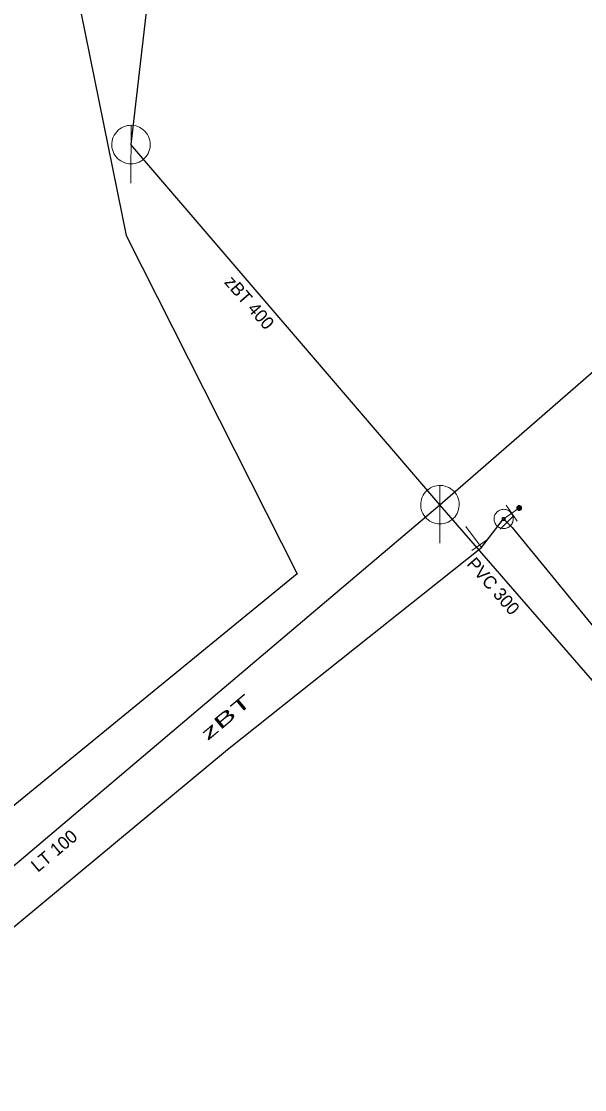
# Model space of a CAD drawing. Extents: x -688296 to -687852, y -973332 to -972816.
# Drawn here: x -688140.2 to -688111, y -973095.5 to -973040 of the extents above; entities that cross this region are included whole.
import ezdxf
from ezdxf.enums import TextEntityAlignment as Align

# ---------------------------------------------------------------- set-up
doc = ezdxf.new("R2010")
doc.units = 0
doc.header["$LTSCALE"] = 0.27
for name, color, linetype, lineweight in [('1', 7, 'Continuous', 25), ('13', 7, 'Continuous', 13), ('14', 7, 'Continuous', 13), ('17', 7, 'Continuous', 25), ('22', 7, 'Continuous', 13), ('34', 7, 'Continuous', 13), ('47', 7, 'Continuous', 13), ('9', 7, 'Continuous', 13)]:
    doc.layers.add(name, color=color, linetype=linetype, lineweight=lineweight)

msp = doc.modelspace()

# ---------------------------------------------------------------- linework, layer by layer
at = {"layer": '13'}
msp.add_line((-688116.42, -973067.199), (-688117.129, -973066.239), dxfattribs=at)
at = {"layer": '14', "lineweight": 25}
for p, q in [((-688134.528, -973046.412), (-688132.125, -973025.78)), ((-688118.48, -973065.11), (-688096.66, -973046.13)), ((-688118.48, -973065.11), (-688134.529, -973046.413)), ((-688141.707, -973084.764), (-688118.48, -973065.11))]:
    msp.add_line(p, q, dxfattribs=at)
at = {"layer": '14'}
for p, q in [((-688115.17, -973065.85), (-688114.989, -973066.03)), ((-688116.32, -973067.34), (-688116.42, -973067.199))]:
    msp.add_line(p, q, dxfattribs=at)
at = {"layer": '14', "lineweight": 25}
msp.add_lwpolyline([(-688102.469, -973083.96), (-688109.289, -973075.699), (-688118.48, -973065.109)], dxfattribs=at)
at = {"layer": '14'}
msp.add_lwpolyline([(-688115.17, -973065.85), (-688114.94, -973065.68), (-688114.75, -973065.55), (-688114.359, -973065.28)], dxfattribs=at)
at = {"layer": '17'}
for points in [[(-688123.609, -972815.609), (-688135.91, -972839.761), (-688146.524, -972867.704), (-688149.164, -972878.87), (-688150.368, -972974.473), (-688134.778, -973051.136), (-688125.903, -973068.701), (-688203.651, -973132.27), (-688148.612, -973199.748), (-688078.631, -973291.807), (-688049.631, -973331.642)], [(-688143.109, -973089.09), (-688129.52, -973077.82), (-688116.32, -973067.34), (-688115.17, -973065.85)], [(-688114.989, -973066.03), (-688114.73, -973066.289), (-688065.039, -973126.929)]]:
    msp.add_lwpolyline(points, dxfattribs=at)
at = {"layer": '22'}
for p, q in [((-688134.529, -973048.413), (-688134.528, -973045.413)), ((-688118.48, -973067.109), (-688118.479, -973064.109))]:
    msp.add_line(p, q, dxfattribs=at)
for points in [[(-688133.529, -973046.413), (-688133.534, -973046.304), (-688133.552, -973046.196), (-688133.582, -973046.09), (-688133.622, -973045.989), (-688133.674, -973045.892), (-688133.736, -973045.802), (-688133.808, -973045.719), (-688133.888, -973045.645), (-688133.976, -973045.579), (-688134.07, -973045.524), (-688134.17, -973045.479), (-688134.275, -973045.446), (-688134.382, -973045.424), (-688134.491, -973045.414), (-688134.601, -973045.416), (-688134.709, -973045.43), (-688134.816, -973045.455), (-688134.919, -973045.492), (-688135.017, -973045.541), (-688135.109, -973045.599), (-688135.195, -973045.668), (-688135.272, -973045.745), (-688135.341, -973045.831), (-688135.4, -973045.923), (-688135.448, -973046.021), (-688135.485, -973046.124), (-688135.511, -973046.231), (-688135.525, -973046.339), (-688135.528, -973046.449), (-688135.518, -973046.558), (-688135.497, -973046.665), (-688135.463, -973046.769), (-688135.419, -973046.869), (-688135.364, -973046.964), (-688135.298, -973047.052), (-688135.224, -973047.132), (-688135.141, -973047.204), (-688135.051, -973047.266), (-688134.955, -973047.318), (-688134.853, -973047.359), (-688134.748, -973047.389), (-688134.64, -973047.407), (-688134.53, -973047.413), (-688134.421, -973047.407), (-688134.313, -973047.389), (-688134.208, -973047.36), (-688134.106, -973047.319), (-688134.009, -973047.267), (-688133.919, -973047.205), (-688133.836, -973047.134), (-688133.761, -973047.054), (-688133.696, -973046.966), (-688133.64, -973046.872), (-688133.596, -973046.772), (-688133.562, -973046.668), (-688133.54, -973046.56), (-688133.53, -973046.451)], [(-688117.48, -973065.109), (-688117.485, -973065), (-688117.503, -973064.892), (-688117.533, -973064.786), (-688117.573, -973064.685), (-688117.625, -973064.588), (-688117.687, -973064.498), (-688117.759, -973064.415), (-688117.839, -973064.341), (-688117.927, -973064.275), (-688118.021, -973064.22), (-688118.121, -973064.175), (-688118.226, -973064.142), (-688118.333, -973064.12), (-688118.442, -973064.11), (-688118.552, -973064.112), (-688118.66, -973064.126), (-688118.767, -973064.151), (-688118.87, -973064.188), (-688118.968, -973064.237), (-688119.06, -973064.295), (-688119.146, -973064.364), (-688119.223, -973064.441), (-688119.292, -973064.527), (-688119.351, -973064.619), (-688119.399, -973064.717), (-688119.436, -973064.82), (-688119.462, -973064.927), (-688119.476, -973065.035), (-688119.479, -973065.145), (-688119.469, -973065.254), (-688119.448, -973065.361), (-688119.414, -973065.465), (-688119.37, -973065.565), (-688119.315, -973065.66), (-688119.249, -973065.748), (-688119.175, -973065.828), (-688119.092, -973065.9), (-688119.002, -973065.962), (-688118.906, -973066.014), (-688118.804, -973066.055), (-688118.699, -973066.085), (-688118.591, -973066.103), (-688118.481, -973066.109), (-688118.372, -973066.103), (-688118.264, -973066.085), (-688118.159, -973066.056), (-688118.057, -973066.015), (-688117.96, -973065.963), (-688117.87, -973065.901), (-688117.787, -973065.83), (-688117.712, -973065.75), (-688117.647, -973065.662), (-688117.591, -973065.568), (-688117.547, -973065.468), (-688117.513, -973065.364), (-688117.491, -973065.256), (-688117.481, -973065.147)]]:
    msp.add_lwpolyline(points, close=True, dxfattribs=at)
at = {"layer": '34'}
for p, q in [((-688115.032, -973065.137), (-688114.468, -973065.962)), ((-688114.635, -973065.676), (-688115.342, -973066.383)), ((-688116.826, -973067.49), (-688116.012, -973066.908))]:
    msp.add_line(p, q, dxfattribs=at)
at = {"layer": '47'}
for points in [[(-688114.864, -973065.454), (-688114.907, -973065.424), (-688114.953, -973065.399), (-688115.001, -973065.379), (-688115.051, -973065.364), (-688115.103, -973065.354), (-688115.155, -973065.35), (-688115.207, -973065.352), (-688115.259, -973065.358), (-688115.31, -973065.37), (-688115.36, -973065.387), (-688115.407, -973065.41), (-688115.451, -973065.437), (-688115.493, -973065.468), (-688115.531, -973065.505), (-688115.565, -973065.544), (-688115.595, -973065.587), (-688115.62, -973065.633), (-688115.64, -973065.682), (-688115.655, -973065.731), (-688115.665, -973065.783), (-688115.669, -973065.835), (-688115.668, -973065.888), (-688115.661, -973065.94), (-688115.65, -973065.99), (-688115.632, -973066.04), (-688115.609, -973066.087), (-688115.582, -973066.132), (-688115.551, -973066.173), (-688115.514, -973066.211), (-688115.475, -973066.245), (-688115.432, -973066.275), (-688115.386, -973066.3), (-688115.338, -973066.321), (-688115.288, -973066.335), (-688115.236, -973066.345), (-688115.184, -973066.35), (-688115.132, -973066.349), (-688115.08, -973066.342), (-688115.029, -973066.33), (-688114.979, -973066.312), (-688114.932, -973066.289), (-688114.887, -973066.263), (-688114.846, -973066.231), (-688114.808, -973066.194), (-688114.774, -973066.155), (-688114.744, -973066.112), (-688114.719, -973066.066), (-688114.699, -973066.018), (-688114.684, -973065.968), (-688114.674, -973065.916), (-688114.669, -973065.864), (-688114.671, -973065.812), (-688114.678, -973065.76), (-688114.69, -973065.709), (-688114.707, -973065.659), (-688114.73, -973065.612), (-688114.757, -973065.568), (-688114.788, -973065.526), (-688114.825, -973065.488)], [(-688115.119, -973065.785), (-688115.127, -973065.779), (-688115.134, -973065.776), (-688115.142, -973065.772), (-688115.15, -973065.77), (-688115.159, -973065.768), (-688115.167, -973065.768), (-688115.176, -973065.768), (-688115.184, -973065.769), (-688115.192, -973065.771), (-688115.201, -973065.774), (-688115.209, -973065.778), (-688115.216, -973065.782), (-688115.222, -973065.787), (-688115.229, -973065.792), (-688115.234, -973065.799), (-688115.24, -973065.807), (-688115.243, -973065.814), (-688115.247, -973065.822), (-688115.249, -973065.83), (-688115.251, -973065.839), (-688115.251, -973065.847), (-688115.251, -973065.856), (-688115.25, -973065.864), (-688115.248, -973065.873), (-688115.245, -973065.881), (-688115.241, -973065.889), (-688115.237, -973065.896), (-688115.232, -973065.902), (-688115.227, -973065.909), (-688115.22, -973065.914), (-688115.212, -973065.92), (-688115.205, -973065.923), (-688115.197, -973065.927), (-688115.189, -973065.929), (-688115.18, -973065.931), (-688115.172, -973065.932), (-688115.163, -973065.931), (-688115.155, -973065.93), (-688115.146, -973065.928), (-688115.138, -973065.925), (-688115.13, -973065.921), (-688115.123, -973065.917), (-688115.117, -973065.912), (-688115.11, -973065.907), (-688115.105, -973065.9), (-688115.099, -973065.892), (-688115.096, -973065.885), (-688115.092, -973065.877), (-688115.09, -973065.869), (-688115.088, -973065.86), (-688115.087, -973065.852), (-688115.088, -973065.843), (-688115.089, -973065.835), (-688115.091, -973065.827), (-688115.094, -973065.818), (-688115.098, -973065.81), (-688115.102, -973065.803), (-688115.107, -973065.797), (-688115.112, -973065.79)]]:
    msp.add_lwpolyline(points, close=True, dxfattribs=at)
at = {"layer": '9'}
for points in [[(-688114.485, -973065.28), (-688114.485, -973065.293), (-688114.483, -973065.306), (-688114.48, -973065.319), (-688114.475, -973065.331), (-688114.469, -973065.343), (-688114.462, -973065.354), (-688114.454, -973065.364), (-688114.444, -973065.374), (-688114.434, -973065.382), (-688114.423, -973065.389), (-688114.411, -973065.395), (-688114.399, -973065.4), (-688114.386, -973065.403), (-688114.373, -973065.405), (-688114.36, -973065.407), (-688114.347, -973065.406), (-688114.334, -973065.404), (-688114.321, -973065.401), (-688114.309, -973065.396), (-688114.297, -973065.39), (-688114.286, -973065.383), (-688114.276, -973065.375), (-688114.266, -973065.365), (-688114.258, -973065.355), (-688114.251, -973065.344), (-688114.245, -973065.332), (-688114.24, -973065.32), (-688114.237, -973065.307), (-688114.235, -973065.294), (-688114.233, -973065.281), (-688114.234, -973065.268), (-688114.236, -973065.255), (-688114.239, -973065.242), (-688114.244, -973065.23), (-688114.25, -973065.218), (-688114.257, -973065.207), (-688114.265, -973065.197), (-688114.275, -973065.187), (-688114.285, -973065.179), (-688114.296, -973065.172), (-688114.308, -973065.166), (-688114.32, -973065.161), (-688114.333, -973065.158), (-688114.346, -973065.156), (-688114.359, -973065.155), (-688114.372, -973065.155), (-688114.385, -973065.157), (-688114.398, -973065.16), (-688114.41, -973065.165), (-688114.422, -973065.171), (-688114.433, -973065.178), (-688114.443, -973065.186), (-688114.453, -973065.196), (-688114.461, -973065.206), (-688114.468, -973065.217), (-688114.474, -973065.229), (-688114.479, -973065.241), (-688114.482, -973065.254), (-688114.484, -973065.267)], [(-688114.465, -973065.28), (-688114.466, -973065.291), (-688114.464, -973065.302), (-688114.461, -973065.313), (-688114.457, -973065.323), (-688114.452, -973065.333), (-688114.446, -973065.342), (-688114.439, -973065.351), (-688114.431, -973065.359), (-688114.422, -973065.366), (-688114.413, -973065.372), (-688114.403, -973065.377), (-688114.393, -973065.381), (-688114.382, -973065.384), (-688114.371, -973065.387), (-688114.36, -973065.387), (-688114.349, -973065.387), (-688114.338, -973065.385), (-688114.327, -973065.382), (-688114.317, -973065.378), (-688114.307, -973065.373), (-688114.298, -973065.367), (-688114.289, -973065.36), (-688114.281, -973065.352), (-688114.274, -973065.343), (-688114.268, -973065.334), (-688114.263, -973065.324), (-688114.259, -973065.314), (-688114.256, -973065.303), (-688114.254, -973065.292), (-688114.253, -973065.281), (-688114.253, -973065.27), (-688114.255, -973065.259), (-688114.258, -973065.248), (-688114.262, -973065.238), (-688114.267, -973065.228), (-688114.273, -973065.219), (-688114.28, -973065.21), (-688114.288, -973065.202), (-688114.297, -973065.195), (-688114.306, -973065.189), (-688114.316, -973065.184), (-688114.326, -973065.18), (-688114.337, -973065.177), (-688114.348, -973065.175), (-688114.359, -973065.175), (-688114.37, -973065.174), (-688114.381, -973065.176), (-688114.392, -973065.179), (-688114.402, -973065.183), (-688114.412, -973065.188), (-688114.421, -973065.194), (-688114.43, -973065.201), (-688114.438, -973065.209), (-688114.445, -973065.218), (-688114.451, -973065.227), (-688114.456, -973065.237), (-688114.46, -973065.247), (-688114.463, -973065.258), (-688114.465, -973065.269)], [(-688114.446, -973065.28), (-688114.446, -973065.289), (-688114.445, -973065.298), (-688114.442, -973065.307), (-688114.439, -973065.315), (-688114.435, -973065.323), (-688114.43, -973065.331), (-688114.424, -973065.338), (-688114.418, -973065.344), (-688114.411, -973065.35), (-688114.403, -973065.355), (-688114.395, -973065.359), (-688114.387, -973065.362), (-688114.378, -973065.365), (-688114.369, -973065.366), (-688114.36, -973065.368), (-688114.351, -973065.367), (-688114.342, -973065.366), (-688114.333, -973065.363), (-688114.325, -973065.36), (-688114.317, -973065.356), (-688114.309, -973065.351), (-688114.302, -973065.345), (-688114.296, -973065.339), (-688114.29, -973065.332), (-688114.285, -973065.324), (-688114.281, -973065.316), (-688114.278, -973065.308), (-688114.275, -973065.299), (-688114.274, -973065.29), (-688114.272, -973065.281), (-688114.273, -973065.272), (-688114.274, -973065.263), (-688114.277, -973065.254), (-688114.28, -973065.246), (-688114.284, -973065.238), (-688114.289, -973065.23), (-688114.295, -973065.223), (-688114.301, -973065.217), (-688114.308, -973065.211), (-688114.316, -973065.206), (-688114.324, -973065.202), (-688114.332, -973065.199), (-688114.341, -973065.196), (-688114.35, -973065.195), (-688114.359, -973065.194), (-688114.368, -973065.194), (-688114.377, -973065.195), (-688114.386, -973065.198), (-688114.394, -973065.201), (-688114.402, -973065.205), (-688114.41, -973065.21), (-688114.417, -973065.216), (-688114.423, -973065.222), (-688114.429, -973065.229), (-688114.434, -973065.237), (-688114.438, -973065.245), (-688114.441, -973065.253), (-688114.444, -973065.262), (-688114.445, -973065.271)], [(-688114.426, -973065.28), (-688114.426, -973065.287), (-688114.425, -973065.294), (-688114.424, -973065.301), (-688114.421, -973065.307), (-688114.418, -973065.313), (-688114.414, -973065.319), (-688114.41, -973065.325), (-688114.405, -973065.33), (-688114.399, -973065.334), (-688114.393, -973065.338), (-688114.387, -973065.341), (-688114.381, -973065.344), (-688114.374, -973065.345), (-688114.367, -973065.348), (-688114.36, -973065.348), (-688114.353, -973065.348), (-688114.346, -973065.346), (-688114.339, -973065.345), (-688114.333, -973065.342), (-688114.326, -973065.339), (-688114.321, -973065.335), (-688114.315, -973065.331), (-688114.31, -973065.326), (-688114.306, -973065.32), (-688114.302, -973065.314), (-688114.299, -973065.308), (-688114.296, -973065.302), (-688114.294, -973065.295), (-688114.293, -973065.288), (-688114.292, -973065.281), (-688114.292, -973065.274), (-688114.293, -973065.267), (-688114.295, -973065.26), (-688114.298, -973065.254), (-688114.301, -973065.247), (-688114.305, -973065.242), (-688114.309, -973065.236), (-688114.314, -973065.231), (-688114.32, -973065.227), (-688114.325, -973065.223), (-688114.332, -973065.22), (-688114.338, -973065.217), (-688114.345, -973065.215), (-688114.352, -973065.214), (-688114.359, -973065.214), (-688114.366, -973065.214), (-688114.373, -973065.214), (-688114.38, -973065.216), (-688114.386, -973065.219), (-688114.392, -973065.222), (-688114.398, -973065.226), (-688114.404, -973065.23), (-688114.409, -973065.235), (-688114.413, -973065.241), (-688114.417, -973065.246), (-688114.42, -973065.253), (-688114.423, -973065.259), (-688114.424, -973065.266), (-688114.426, -973065.273)], [(-688114.406, -973065.28), (-688114.406, -973065.285), (-688114.406, -973065.29), (-688114.405, -973065.295), (-688114.403, -973065.299), (-688114.401, -973065.304), (-688114.398, -973065.308), (-688114.395, -973065.311), (-688114.391, -973065.315), (-688114.388, -973065.318), (-688114.384, -973065.321), (-688114.379, -973065.323), (-688114.375, -973065.325), (-688114.37, -973065.326), (-688114.365, -973065.328), (-688114.36, -973065.328), (-688114.355, -973065.328), (-688114.35, -973065.327), (-688114.345, -973065.326), (-688114.341, -973065.324), (-688114.336, -973065.322), (-688114.332, -973065.319), (-688114.328, -973065.316), (-688114.325, -973065.312), (-688114.322, -973065.309), (-688114.319, -973065.305), (-688114.317, -973065.3), (-688114.315, -973065.296), (-688114.314, -973065.291), (-688114.313, -973065.286), (-688114.312, -973065.281), (-688114.312, -973065.276), (-688114.313, -973065.271), (-688114.314, -973065.266), (-688114.316, -973065.262), (-688114.318, -973065.257), (-688114.321, -973065.253), (-688114.324, -973065.249), (-688114.327, -973065.246), (-688114.331, -973065.243), (-688114.335, -973065.24), (-688114.34, -973065.238), (-688114.344, -973065.236), (-688114.349, -973065.235), (-688114.354, -973065.234), (-688114.359, -973065.234), (-688114.364, -973065.234), (-688114.369, -973065.235), (-688114.374, -973065.235), (-688114.378, -973065.237), (-688114.383, -973065.239), (-688114.387, -973065.242), (-688114.39, -973065.245), (-688114.394, -973065.248), (-688114.397, -973065.252), (-688114.4, -973065.256), (-688114.402, -973065.261), (-688114.404, -973065.265), (-688114.405, -973065.27), (-688114.406, -973065.275)], [(-688114.386, -973065.28), (-688114.386, -973065.283), (-688114.387, -973065.286), (-688114.386, -973065.288), (-688114.385, -973065.291), (-688114.384, -973065.294), (-688114.382, -973065.296), (-688114.38, -973065.298), (-688114.378, -973065.3), (-688114.376, -973065.302), (-688114.374, -973065.304), (-688114.371, -973065.306), (-688114.368, -973065.307), (-688114.366, -973065.307), (-688114.363, -973065.308), (-688114.36, -973065.308), (-688114.357, -973065.308), (-688114.354, -973065.308), (-688114.351, -973065.307), (-688114.349, -973065.306), (-688114.346, -973065.305), (-688114.344, -973065.303), (-688114.341, -973065.301), (-688114.339, -973065.299), (-688114.338, -973065.297), (-688114.336, -973065.295), (-688114.335, -973065.292), (-688114.333, -973065.289), (-688114.333, -973065.287), (-688114.332, -973065.284), (-688114.331, -973065.281), (-688114.332, -973065.278), (-688114.332, -973065.275), (-688114.333, -973065.272), (-688114.334, -973065.27), (-688114.335, -973065.267), (-688114.337, -973065.265), (-688114.338, -973065.262), (-688114.34, -973065.26), (-688114.343, -973065.259), (-688114.345, -973065.257), (-688114.348, -973065.256), (-688114.35, -973065.255), (-688114.353, -973065.254), (-688114.356, -973065.254), (-688114.359, -973065.253), (-688114.362, -973065.254), (-688114.365, -973065.253), (-688114.367, -973065.255), (-688114.37, -973065.255), (-688114.373, -973065.256), (-688114.375, -973065.258), (-688114.377, -973065.259), (-688114.379, -973065.261), (-688114.381, -973065.264), (-688114.383, -973065.266), (-688114.384, -973065.269), (-688114.385, -973065.271), (-688114.386, -973065.274), (-688114.386, -973065.277)], [(-688114.367, -973065.28), (-688114.367, -973065.282), (-688114.367, -973065.282), (-688114.366, -973065.282), (-688114.366, -973065.284), (-688114.367, -973065.285), (-688114.365, -973065.285), (-688114.365, -973065.285), (-688114.365, -973065.287), (-688114.365, -973065.287), (-688114.364, -973065.288), (-688114.362, -973065.288), (-688114.362, -973065.288), (-688114.362, -973065.289), (-688114.36, -973065.289), (-688114.36, -973065.289), (-688114.359, -973065.289), (-688114.358, -973065.289), (-688114.358, -973065.288), (-688114.357, -973065.288), (-688114.355, -973065.288), (-688114.355, -973065.287), (-688114.355, -973065.287), (-688114.354, -973065.286), (-688114.354, -973065.286), (-688114.352, -973065.285), (-688114.352, -973065.284), (-688114.351, -973065.283), (-688114.351, -973065.283), (-688114.351, -973065.282), (-688114.351, -973065.281), (-688114.351, -973065.28), (-688114.351, -973065.279), (-688114.351, -973065.279), (-688114.352, -973065.278), (-688114.352, -973065.277), (-688114.353, -973065.276), (-688114.353, -973065.276), (-688114.354, -973065.275), (-688114.354, -973065.275), (-688114.355, -973065.274), (-688114.356, -973065.274), (-688114.357, -973065.273), (-688114.357, -973065.273), (-688114.358, -973065.273), (-688114.359, -973065.273), (-688114.36, -973065.273), (-688114.361, -973065.273), (-688114.361, -973065.273), (-688114.362, -973065.274), (-688114.363, -973065.273), (-688114.364, -973065.275), (-688114.364, -973065.275), (-688114.365, -973065.275), (-688114.365, -973065.275), (-688114.366, -973065.277), (-688114.366, -973065.278), (-688114.366, -973065.279), (-688114.367, -973065.279), (-688114.367, -973065.28)]]:
    msp.add_lwpolyline(points, close=True, dxfattribs=at)

# ---------------------------------------------------------------- texts
at = {"layer": '1'}
for s, rotation, p in [('zBT 400 ', 311, (-688128.5447, -973054.9241)), ('zBT 400 ', 311, (-688128.5447, -973054.9241)), ('zBT 400 ', 311, (-688128.5447, -973054.9241)), ('zBT 400 ', 311, (-688128.5447, -973054.9241)), ('zBT 400 ', 311, (-688128.5447, -973054.9241)), ('PVC 300 ', 311, (-688115.8762, -973069.6482)), ('PVC 300 ', 311, (-688115.8762, -973069.6482)), ('PVC 300 ', 311, (-688115.8762, -973069.6482)), ('PVC 300 ', 311, (-688115.8762, -973069.6482)), ('PVC 300 ', 311, (-688115.8762, -973069.6482)), ('LT 100', 40, (-688138.3072, -973083.3327)), ('LT 100', 40, (-688138.3072, -973083.3327)), ('LT 100', 40, (-688138.3072, -973083.3327)), ('LT 100', 40, (-688138.3072, -973083.3327)), ('LT 100', 40, (-688138.3072, -973083.3327))]:
    msp.add_text(s, height=0.6667, rotation=rotation, dxfattribs=at).set_placement(p, align=Align.CENTER)
at = {"layer": '1', "width": 1.95}
msp.add_text('zBT   ', height=0.6667, rotation=40, dxfattribs=at).set_placement((-688128.8183, -973075.9356), align=Align.CENTER)
msp.add_text('zBT   ', height=0.6667, rotation=40, dxfattribs=at).set_placement((-688128.8183, -973075.9356), align=Align.CENTER)
msp.add_text('zBT   ', height=0.6667, rotation=40, dxfattribs=at).set_placement((-688128.8183, -973075.9356), align=Align.CENTER)
msp.add_text('zBT   ', height=0.6667, rotation=40, dxfattribs=at).set_placement((-688128.8183, -973075.9356), align=Align.CENTER)
msp.add_text('zBT   ', height=0.6667, rotation=40, dxfattribs=at).set_placement((-688128.8183, -973075.9356), align=Align.CENTER)

doc.saveas('drawing.dxf')
